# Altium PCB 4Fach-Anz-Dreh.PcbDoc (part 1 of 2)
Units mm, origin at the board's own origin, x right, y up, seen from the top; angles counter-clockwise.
Board outline 160 x 100 mm, 2 copper layers (Top Layer, Bottom Layer), stack 1.601 mm thick; 204 components, 197 nets, 945 pads, 254 vias.
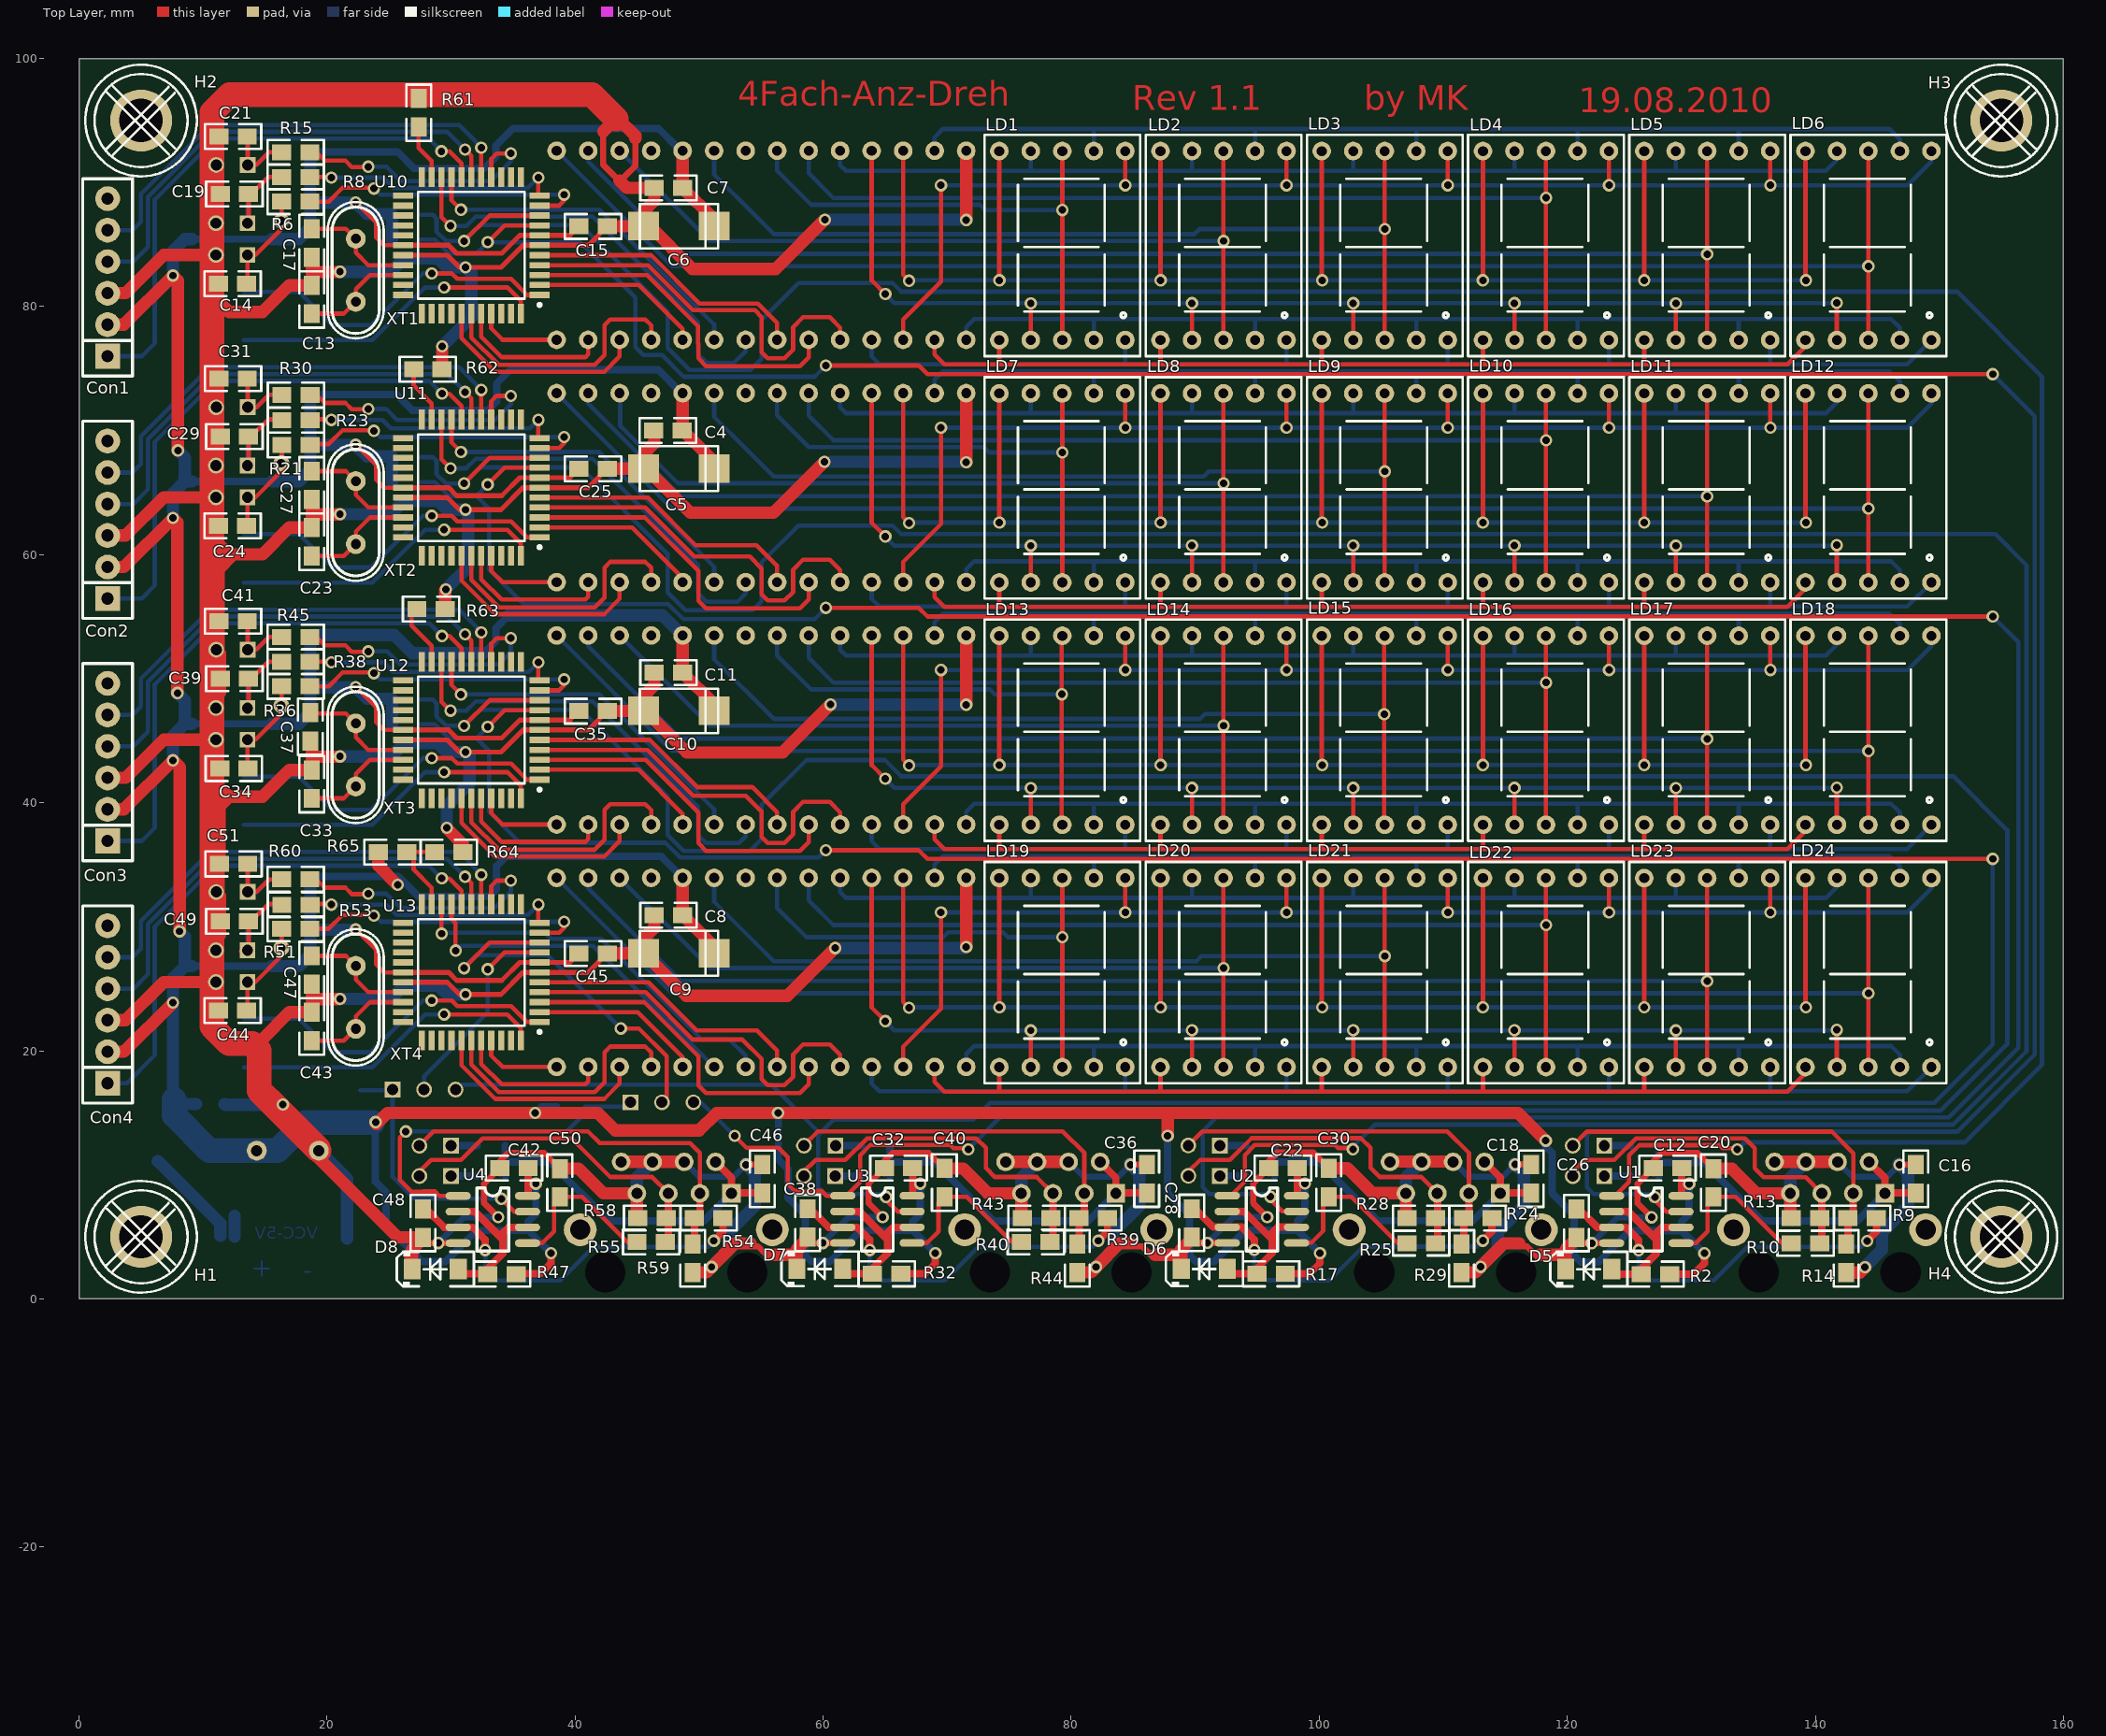
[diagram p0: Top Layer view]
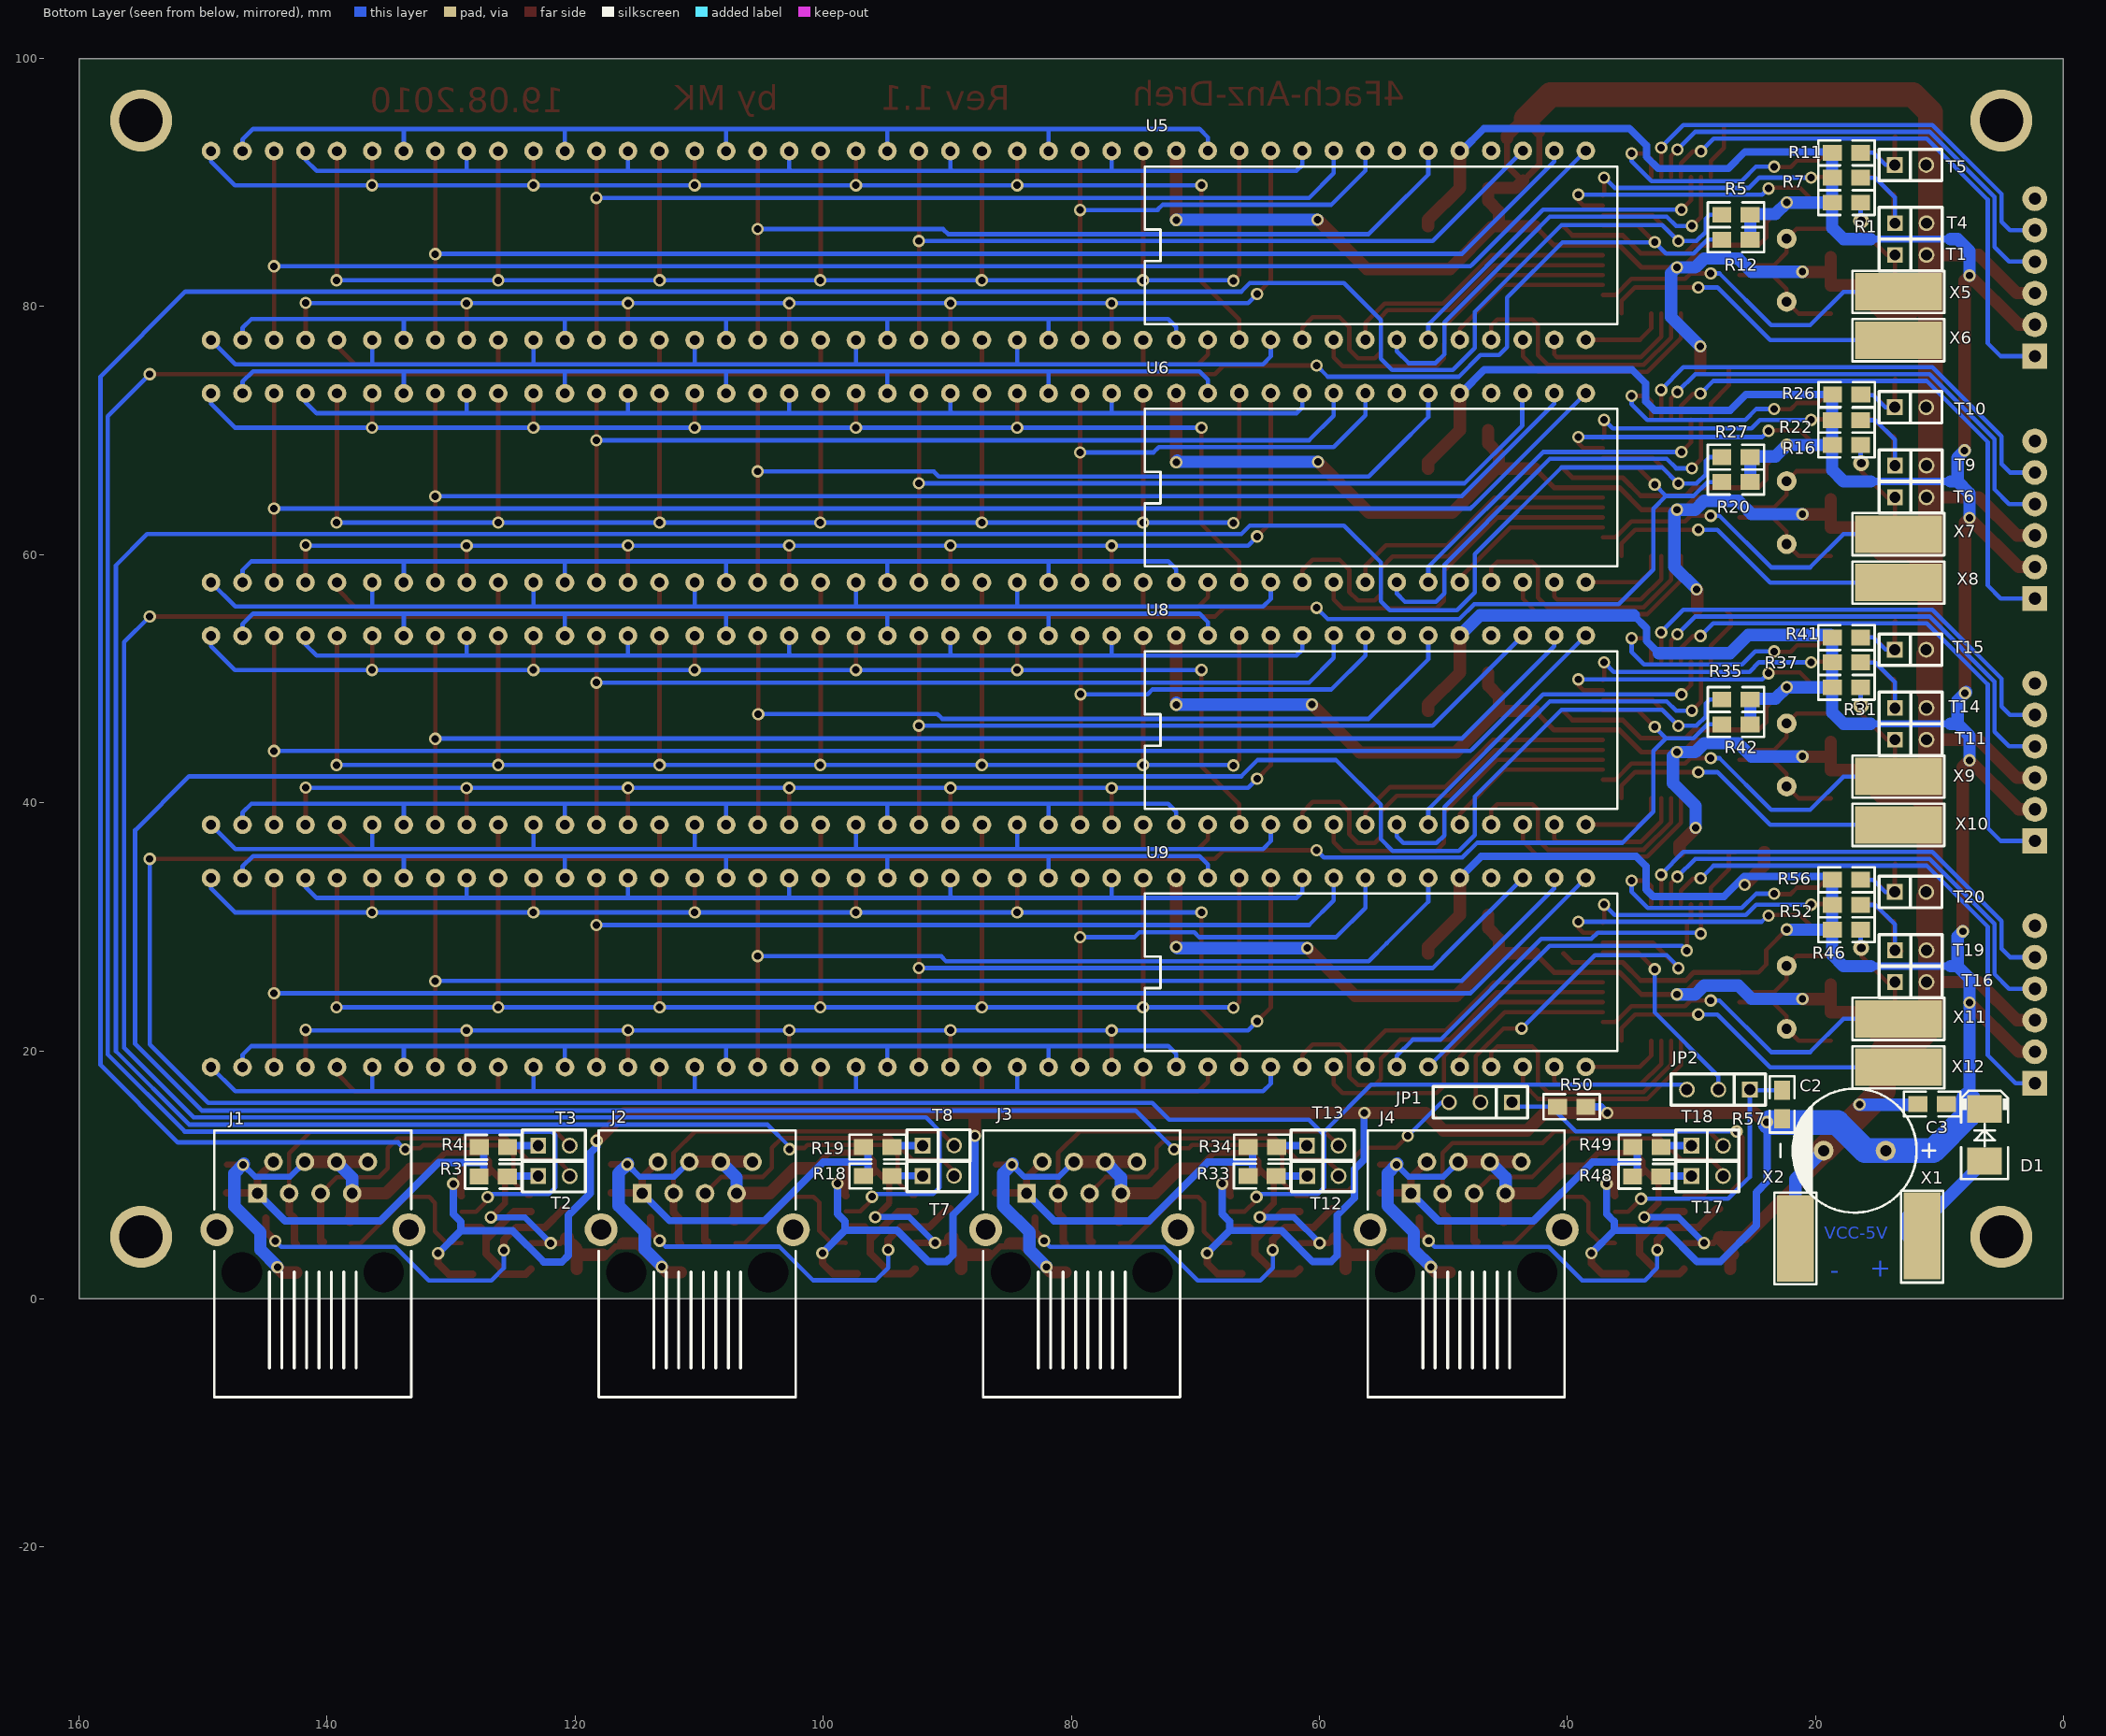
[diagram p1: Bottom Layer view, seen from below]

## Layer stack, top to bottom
Top Layer: signal copper 0.0356
Dielectric: core 1.53, FR-4, Dk 4.8
Bottom Layer: signal copper 0.0356

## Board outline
0,0 160,0 160,100 0,100

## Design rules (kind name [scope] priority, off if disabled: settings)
Clearance [All] p1: gap=0.2
ComponentClearance [All] p1 off: gap=0.254 collisioncheckmode=3 verticalgap=0 showdistances=FALSE
HoleSize [All] p1: absolutevalues=TRUE maxlimit=10 minlimit=0.2 maxpercent=80.000 minpercent=20.000
PlaneConnect [All] p1: planeconnectstyle=Relief reliefexpansion=0.5 reliefentries=4 reliefconductorwidth=0.2 reliefairgap=0.2
PolygonConnect [All] p1: connectstyle=Direct reliefconductorwidth=1 reliefentries=4 polygonreliefangle="90 Angle"
RoutingVias [All] p1: holewidth=0.4 width=0.8 viastyle="Through Hole" minholewidth=0.4 minwidth=0.8 maxholewidth=1 maxwidth=2
SolderMaskExpansion [All] p1: expansion=0.102
TestPointUsage [All] p1: valid=0 allowmultiple=FALSE
Testpoint [All] p1: side=3 testpointundercomponent=TRUE minsize=1.016 maxsize=2.54 preferedsize=1.524 minholesize=0 maxholesize=1.016 preferedholesize=0.813 testpointgrid=0.025 style=297 order=0123456789
Width [All] p1: maxlimit=10 minlimit=0.2 preferedwidth=0.5
16 further rules are at their usual default settings.

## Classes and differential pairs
component class PIC-3-4: C32 C33 C34 C35 C36 C37 C38 C39 C40 C41 C42 C43 C44 C45 C46 C47 C48 C49 C50 C51 Con3 Con4 D7 D8 J3 J4 JP1 JP2 R31 R32 R33 R34 R35 R36 R37 R38 R39 R40 R41 R42 R43 R44 R45 R46 R47 R48 R49 R50 R51 R52 R53 R54 R55 R56 R57 R58 R59 R60 R63 R64 R65 T11 T12 T13 T14 T15 T16 T17 T18 T19 T20 U3 U4 U12 U13 X9 X10 X11 X12 XT3 XT4
component class PIC-1-2: C12 C13 C14 C15 C16 C17 C18 C19 C20 C21 C22 C23 C24 C25 C26 C27 C28 C29 C30 C31 Con1 Con2 D5 D6 H1 H2 H3 H4 J1 J2 R1 R2 R3 R4 R5 R6 R7 R8 R9 R10 R11 R12 R13 R14 R15 R16 R17 R18 R19 R20 R21 R22 R23 R24 R25 R26 R27 R28 R29 R30 R61 R62 T1 T2 T3 T4 T5 T6 T7 T8 T9 T10 U1 U2 U10 U11 X5 X6 X7 X8 XT1 XT2
component class Display-3-4: C8 C9 C10 C11 LD13 LD14 LD15 LD16 LD17 LD18 LD19 LD20 LD21 LD22 LD23 LD24 U8 U9
component class Display-1-2: C2 C3 C4 C5 C6 C7 D1 LD1 LD2 LD3 LD4 LD5 LD6 LD7 LD8 LD9 LD10 LD11 LD12 U5 U6 X1 X2

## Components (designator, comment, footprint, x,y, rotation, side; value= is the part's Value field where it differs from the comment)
C2 "1000uF" ELK_RM050_10x12.5 16.83,11.95 r0 bottom
C3 "100nF" 0805 9.44,15.71 r0 bottom
C4 "100nF" 0805 48.63,70.02 r180 top
C5 "47uF 16V" Bauform_C 51.52,66.94 r180 top
C6 "47uF 16V" Bauform_C 51.52,86.48 r180 top locked
C7 "100nF" 0805 48.67,89.56 r180 top locked
C8 "100nF" 0805 48.67,30.94 r180 top
C9 "47uF 16V" Bauform_C 51.52,27.86 r180 top
C10 "47uF 16V" Bauform_C 51.52,47.4 r180 top
C11 "100nF" 0805 48.67,50.48 r180 top
C12 "100NF" 0805 129.22,10.54 r180 top locked
C13 "22PF" 0805 18.76,79.43 r90 top locked
C14 "100NF" 0805 13.52,81.85 r180 top locked
C15 "100nF" 0805 40.3,86.46 r0 top locked
C16 "100NF" 0805 148.09,8.53 r90 top locked
C17 "22PF" 0805 18.76,86.27 r270 top locked
C18 "100pF" 0805 120.74,7.25 r270 top locked
C19 "100NF" 0805 13.67,89.07 r180 top locked
C20 "100pF" 0805 131.77,8.21 r90 top locked
C21 "100NF" 0805 13.56,93.72 r180 top locked
C22 "100NF" 0805 98.22,10.55 r180 top
C23 "22PF" 0805 18.76,59.89 r90 top
C24 "100NF" 0805 13.52,62.31 r180 top
C25 "100nF" 0805 40.3,66.93 r0 top
C26 "100NF" 0805 117.09,8.54 r90 top
C27 "22PF" 0805 18.76,66.73 r270 top
C28 "100pF" 0805 89.71,7.26 r270 top
C29 "100NF" 0805 13.67,69.53 r180 top
C30 "100pF" 0805 100.77,8.22 r90 top
C31 "100NF" 0805 13.56,74.18 r180 top
C32 "100NF" 0805 67.22,10.55 r180 top
C33 "22PF" 0805 18.76,40.35 r90 top
C34 "100NF" 0805 13.63,42.75 r180 top
C35 "100nF" 0805 40.3,47.38 r0 top
C36 "100NF" 0805 86.09,8.54 r90 top
C37 "22PF" 0805 18.64,47.27 r270 top
C38 "100pF" 0805 58.74,7.26 r270 top
C39 "100NF" 0805 13.67,49.99 r180 top
C40 "100pF" 0805 69.77,8.22 r90 top
C41 "100NF" 0805 13.56,54.64 r180 top
C42 "100NF" 0805 36.21,10.54 r180 top
C43 "22PF" 0805 18.76,20.81 r90 top
C44 "100NF" 0805 13.52,23.23 r180 top
C45 "100nF" 0805 40.3,27.84 r0 top
C46 "100NF" 0805 55.08,8.53 r90 top
C47 "22PF" 0805 18.76,27.65 r270 top
C48 "100pF" 0805 27.73,7.25 r270 top
C49 "100NF" 0805 13.67,30.45 r180 top
C50 "100pF" 0805 38.76,8.21 r90 top
C51 "100NF" 0805 13.6,35.06 r180 top
Con1 "Con_6" Con_6 2.3,76 r90 top locked
Con2 "Con_6" Con_6 2.3,56.46 r90 top
Con3 "Con_6" Con_6 2.3,36.92 r90 top
Con4 "Con_6" Con_6 2.3,17.38 r90 top
D1 "MBRS140T3(R)" SMB 6.35,11.11 r270 bottom
D5 "LL4148" MINIMELF 123.58,2.4 r270 top locked
D6 "LL4148" MINIMELF 92.58,2.41 r270 top
D7 "LL4148" MINIMELF 61.58,2.41 r270 top
D8 "LL4148" MINIMELF 30.57,2.4 r270 top
H1 "Hole 3,5mm" "Hole 3,5mm" 5,5 r0 top locked
H2 "Hole 3,5mm" "Hole 3,5mm" 5,95 r0 top locked
H3 "Hole 3,5mm" "Hole 3,5mm" 155,95 r0 top locked
H4 "Hole 3,5mm" "Hole 3,5mm" 155,5 r0 top locked
J1 "MEBP 8-8G" "RJ45-JACK-MEBP 8-8G" 145.6,8.5 r180 bottom locked
J2 "MEBP 8-8G" "RJ45-JACK-MEBP 8-8G" 114.6,8.5 r180 bottom locked
J3 "MEBP 8-8G" "RJ45-JACK-MEBP 8-8G" 83.6,8.5 r180 bottom locked
J4 "MEBP 8-8G" "RJ45-JACK-MEBP 8-8G" 52.6,8.5 r180 bottom
JP1 "Jumper" SIP3 44.46,15.84 r0 bottom
JP2 "Jumper" SIP3 25.28,16.87 r0 bottom
LD1 "SA52-11" SA52-11 73,76 r0 top locked
LD2 "SA52-11" SA52-11 86,76 r0 top locked
LD3 "SA52-11" SA52-11 99,76 r0 top locked
LD4 "SA52-11" SA52-11 112,76 r0 top locked
LD5 "SA52-11" SA52-11 125,76 r0 top locked
LD6 "SA52-11" SA52-11 138,76 r0 top locked
LD7 "SA52-11" SA52-11 73,56.46 r0 top
LD8 "SA52-11" SA52-11 86,56.46 r0 top
LD9 "SA52-11" SA52-11 99,56.46 r0 top
LD10 "SA52-11" SA52-11 112,56.46 r0 top
LD11 "SA52-11" SA52-11 125,56.46 r0 top
LD12 "SA52-11" SA52-11 138,56.46 r0 top
LD13 "SA52-11" SA52-11 73,36.92 r0 top
LD14 "SA52-11" SA52-11 86,36.92 r0 top
LD15 "SA52-11" SA52-11 99,36.92 r0 top
LD16 "SA52-11" SA52-11 112,36.92 r0 top
LD17 "SA52-11" SA52-11 125,36.92 r0 top
LD18 "SA52-11" SA52-11 138,36.92 r0 top
LD19 "SA52-11" SA52-11 73,17.38 r0 top
LD20 "SA52-11" SA52-11 86,17.38 r0 top
LD21 "SA52-11" SA52-11 99,17.38 r0 top
LD22 "SA52-11" SA52-11 112,17.38 r0 top
LD23 "SA52-11" SA52-11 125,17.38 r0 top
LD24 "SA52-11" SA52-11 138,17.38 r0 top
R1 "1k" 0805 18.64,88.38 r180 bottom locked
R2 "1k" 0805 128.26,2 r180 top locked
R3 "1k" 0805 127.75,9.88 r180 bottom locked
R4 "1k" 0805 127.74,12.22 r180 bottom locked
R5 "1k" 0805 27.54,87.4 r180 bottom locked
R6 "1k" 0805 16.32,88.46 r0 top locked
R7 "1k" 0805 18.64,90.38 r180 bottom locked
R8 "1k" 0805 16.32,90.45 r0 top locked
R9 "1k" 0805 144.92,6.51 r180 top locked
R10 "1k" 0805 140.36,4.48 r180 top locked
R11 "1k" 0805 18.64,92.4 r180 bottom locked
R12 "1k" 0805 27.54,85.39 r180 bottom locked
R13 "100k" 0805 140.36,6.51 r180 top locked
R14 "100k" 0805 142.48,4.41 r270 top locked
R15 "1k" 0805 16.32,92.44 r0 top locked
R16 "1k" 0805 18.64,68.84 r180 bottom
R17 "1k" 0805 97.26,2.01 r180 top
R18 "1k" 0805 96.75,9.89 r180 bottom
R19 "1k" 0805 96.74,12.23 r180 bottom
R20 "1k" 0805 27.54,67.86 r180 bottom
R21 "1k" 0805 16.35,68.84 r0 top
R22 "1k" 0805 18.64,70.84 r180 bottom
R23 "1k" 0805 16.35,70.84 r0 top
R24 "1k" 0805 113.92,6.52 r180 top
R25 "1k" 0805 109.36,4.49 r180 top
R26 "1k" 0805 18.61,72.9 r180 bottom
R27 "1k" 0805 27.54,65.85 r180 bottom
R28 "100k" 0805 109.36,6.52 r180 top
R29 "100k" 0805 111.48,4.42 r270 top
R30 "1k" 0805 16.35,72.86 r0 top
R31 "1k" 0805 18.64,49.3 r180 bottom
R32 "1k" 0805 66.26,2.01 r180 top
R33 "1k" 0805 65.75,9.89 r180 bottom
R34 "1k" 0805 65.74,12.23 r180 bottom
R35 "1k" 0805 27.54,48.32 r180 bottom
R36 "1k" 0805 16.32,49.38 r0 top
R37 "1k" 0805 18.64,51.3 r180 bottom
R38 "1k" 0805 16.32,51.37 r0 top
R39 "1k" 0805 82.92,6.52 r180 top
R40 "1k" 0805 78.29,4.59 r180 top
R41 "1k" 0805 18.64,53.32 r180 bottom
R42 "1k" 0805 27.54,46.31 r180 bottom
R43 "100k" 0805 78.36,6.52 r180 top
R44 "100k" 0805 80.48,4.42 r270 top
R45 "1k" 0805 16.32,53.36 r0 top
R46 "1k" 0805 18.64,29.76 r180 bottom
R47 "1k" 0805 35.25,2 r180 top
R48 "1k" 0805 34.74,9.88 r180 bottom
R49 "1k" 0805 34.73,12.22 r180 bottom
R50 "1k" 0805 40.8,15.49 r180 bottom
R51 "1k" 0805 16.32,29.84 r0 top
R52 "1k" 0805 18.64,31.76 r180 bottom
R53 "1k" 0805 16.35,31.76 r0 top
R54 "1k" 0805 51.91,6.51 r180 top
R55 "1k" 0805 47.28,4.58 r180 top
R56 "1k" 0805 18.64,33.78 r180 bottom
R57 "1k" 0805 22.68,16.82 r270 bottom
R58 "100k" 0805 47.35,6.51 r180 top
R59 "100k" 0805 49.47,4.41 r270 top
R60 "1k" 0805 16.32,33.82 r0 top
R61 "100k" 0805 27.38,94.48 r90 top
R62 "100k" 0805 29.27,74.95 r180 top
R63 "100k" 0805 29.53,55.62 r180 top
R64 "100k" 0805 28.67,36.025 r0 top
R65 "100k" 0805 26.42,36.025 r180 top
T1 "Taster" SIP2 13.58,84.16 r180 bottom locked
T2 "Taster" SIP2 122.98,9.89 r180 bottom locked
T3 "Taster" SIP2 122.98,12.35 r180 bottom locked
T4 "Taster" SIP2 13.58,86.72 r180 bottom locked
T5 "Taster" SIP2 13.6,91.42 r180 bottom locked
T6 "Taster" SIP2 13.58,64.62 r180 bottom
T7 "Taster" SIP2 91.99,9.91 r180 bottom
T8 "Taster" SIP2 91.98,12.36 r180 bottom
T9 "Taster" SIP2 13.58,67.18 r180 bottom
T10 "Taster" SIP2 13.6,71.88 r180 bottom
T11 "Taster" SIP2 13.58,45.08 r180 bottom
T12 "Taster" SIP2 60.98,9.9 r180 bottom
T13 "Taster" SIP2 60.99,12.35 r180 bottom
T14 "Taster" SIP2 13.58,47.64 r180 bottom
T15 "Taster" SIP2 13.6,52.34 r180 bottom
T16 "Taster" SIP2 13.58,25.54 r180 bottom
T17 "Taster" SIP2 29.98,9.9 r180 bottom
T18 "Taster" SIP2 29.98,12.34 r180 bottom
T19 "Taster" SIP2 13.58,28.1 r180 bottom
T20 "Taster" SIP2 13.6,32.8 r180 bottom
U1 "LM393M" SO-8 123.58,8.3 r0 top locked
U2 "LM393M" SO-8 92.58,8.31 r0 top
U3 "LM393M" SO-8 61.58,8.31 r0 top
U4 "LM393M" SO-8 30.57,8.3 r0 top
U5 "ICM7218AIJI" ICM7218AIJM 71.53,77.32 r90 bottom locked
U6 "ICM7218AIJI" ICM7218AIJM 71.53,57.78 r90 bottom
U8 "ICM7218AIJI" ICM7218AIJM 71.53,38.24 r90 bottom
U9 "ICM7218AIJI" ICM7218AIJM 71.53,18.7 r90 bottom
U10 "16F887" TQFP-44 37.13,80.94 r180 top locked
U11 "16F887" TQFP-44 37.13,61.4 r180 top
U12 "16F887" TQFP-44 37.13,41.86 r180 top
U13 "16F887" TQFP-44 37.13,22.32 r180 top
X1 "Ground" GND_PAD3#1 11.39,5.01 r270 bottom
X2 "Ground" GND_PAD3#2 21.6,4.87 r270 bottom
X5 "Ground" GND_PAD3#2 13.3,81.19 r0 bottom locked
X6 "Ground" GND_PAD3#2 13.3,77.29 r0 bottom locked
X7 "Ground" GND_PAD3#2 13.3,61.65 r180 bottom
X8 "Ground" GND_PAD3#2 13.3,57.75 r0 bottom
X9 "Ground" GND_PAD3#2 13.3,42.11 r180 bottom
X10 "Ground" GND_PAD3#2 13.3,38.21 r0 bottom
X11 "Ground" GND_PAD3#2 13.3,22.57 r180 bottom
X12 "Ground" GND_PAD3#2 13.3,18.67 r0 bottom
XT1 "20MHz" HC-49/U_ST 22.31,80.39 r90 top locked
XT2 "20MHz" HC-49/U_ST 22.31,60.85 r90 top
XT3 "20MHz" HC-49/U_ST 22.31,41.31 r90 top
XT4 "20MHz" HC-49/U_ST 22.31,21.77 r90 top

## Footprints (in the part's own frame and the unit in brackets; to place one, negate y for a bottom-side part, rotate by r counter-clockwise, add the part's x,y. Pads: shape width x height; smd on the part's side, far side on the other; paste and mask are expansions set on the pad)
0805 [mm] "0805_0_0197_R"
  rect 1.54x1.28 smd: 1(0,0) 2(2.29,0)
  silkscreen extent -1.13,-1 3.42,1
Bauform_C [mm] "Tantal 47uF 16V 6032"
  rect 2.5x2.3 smd: 1(0.3,0) 2(6,0)
  silkscreen extent 0,-1.8 6.3,1.8
Con_6 [mm] "Pic-Prog-Connector"
  rect 2x2 hole 1: 1(0,0)
  round 2 hole 1: 2(2.54,0) 3(5.08,0) 4(7.62,0) 5(10.16,0) 6(12.7,0)
  silkscreen extent -1.6,-2 14.3,2
ELK_RM050_10x12.5 [mm]
  round 1.6 hole 0.9: 1(-2.5,0) 2(2.5,0)
  silkscreen extent -6.5,-5 5.99,5
GND_PAD3#1 [mm]
  rect 7x3 smd: 1(-0.06,0)
  silkscreen extent -3.7,-1.7 3.7,1.7
GND_PAD3#2 [mm]
  rect 7x3 smd: 1(0,0)
  silkscreen extent -3.7,-1.7 3.7,1.7
HC-49/U_ST [mm]
  round 1.6 hole 0.8: 1(0,0) 2(5.08,0)
  silkscreen extent -2.96,-2.25 8.04,2.27
"Hole 3,5mm" [mm]
  round 5 hole 3.5: 1(0,0)
  silkscreen extent -4.5,-4.5 4.5,4.5
ICM7218AIJM [mm] "7-Segment Driver"
  round 1.5 hole 0.8: 1(0,0) 2(0,-2.54) 3(0,-5.08) 4(0,-7.62) 5(0,-10.16) 6(0,-12.7) 7(0,-15.24) 8(0,-17.78) 9(0,-20.32) 10(0,-22.86) 11(0,-25.4) 12(0,-27.94) 13(0,-30.48) 14(0,-33.02) 15(15.24,-33.02) 16(15.24,-30.48) 17(15.24,-27.94) 18(15.24,-25.4) 19(15.24,-22.86) 20(15.24,-20.32) 21(15.24,-17.78) 22(15.24,-15.24) 23(15.24,-12.7) 24(15.24,-10.16) 25(15.24,-7.62) 26(15.24,-5.08) 27(15.24,-2.54) 28(15.24,0)
  silkscreen extent 1.27,-35.56 13.97,2.54
MINIMELF [mil]
  rect 64x54 smd: A(0,0) K(0,-146)
  silkscreen extent -55,-195 55,50
"RJ45-JACK-MEBP 8-8G" [mm] "Connector; PCB Jack, Thru-Hole; 1-Port, 8 Positions, 8 Loaded; Shielded without Lightpipes; Left Angle"
  rect 1.5x1.5 hole 0.9: 1(0,0)
  round 1.5 hole 0.9: 2(1.27,2.54) 3(2.54,0) 4(3.81,2.54) 5(5.08,0) 6(6.35,2.54) 7(7.62,0) 8(8.89,2.54)
  round 2.65 hole 1.6: MH1(-3.3,-2.921) MH2(12.19,-2.921)
  round 2.95 hole 3.25: MH3(-1.27,-6.35) MH4(10.16,-6.35)
  silkscreen extent -3.49,-16.42 12.38,5.08
SA52-11 [mm] "7-Segment-Anzeige 13mm"
  round 1.5 hole 0.8: 1(1.2,1.3) 2(3.74,1.3) 3(6.28,1.3) 4(8.82,1.3) 5(11.36,1.3) 6(11.36,16.54) 7(8.82,16.54) 8(6.28,16.54) 9(3.74,16.54) 10(1.2,16.54)
  silkscreen extent 0,0 12.56,17.84
SIP2 [mm]
  rect 1.27x1.27 hole 0.9: 1(0,0)
  round 1.27 hole 0.9: 2(2.54,0)
  silkscreen extent -1.27,-1.27 3.81,1.27
SIP3 [mm]
  rect 1.27x1.27 hole 0.9: 1(0,0)
  round 1.27 hole 0.9: 2(2.54,0) 3(5.08,0)
  silkscreen extent -1.27,-1.27 6.35,1.27
SMB [mm]
  rect 2.2x2.8 smd: A(0,0) K(-4.2,0)
  silkscreen extent -5.66,-1.9 1.46,1.9
SO-8 [mil]
  oval 80x24 smd: 1(0,0) 2(0,-50) 3(0,-100) 4(0,-150) 5(220,-150) 6(220,-100) 7(220,-50) 8(220,0)
  silkscreen extent 60,-175 160,25
TQFP-44 [mm]
  rect 1.6x0.5 smd: 1(0,0) 2(0,-0.8) 3(0,-1.6) 4(0,-2.4) 5(0,-3.2) 6(0,-4) 7(0,-4.8) 8(0,-5.6) 9(0,-6.4) 10(0,-7.2) 11(0,-8) 23(11,-8) 24(11,-7.2) 25(11,-6.4) 26(11,-5.6) 27(11,-4.8) 28(11,-4) 29(11,-3.2) 30(11,-2.4) 31(11,-1.6) 32(11,-0.8) 33(11,0)
  rect 0.5x1.6 smd: 12(1.5,-9.5) 13(2.3,-9.5) 14(3.1,-9.5) 15(3.9,-9.5) 16(4.7,-9.5) 17(5.5,-9.5) 18(6.3,-9.5) 19(7.1,-9.5) 20(7.9,-9.5) 21(8.7,-9.5) 22(9.5,-9.5) 34(9.5,1.5) 35(8.7,1.5) 36(7.9,1.5) 37(7.1,1.5) 38(6.3,1.5) 39(5.5,1.5) 40(4.7,1.5) 41(3.9,1.5) 42(3.1,1.5) 43(2.3,1.5) 44(1.5,1.5)
  silkscreen extent -0.13,-8.3 9.8,0.92

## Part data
C2: library part 1000UF_RM5_25V, "Capacitor Aluminum Electrolytic, 1000UF, 25V, 20%, 105°C, Low impedance"
C3 C4 C7 C8 C11 C12 C14 C15 C16 C19 C21 C22 C24 C25 C26 C29 C31 C32 C34 C35 C36 C39 C41 C42 C44 C45 C46 C49 C51: library part 100NF_0805, "SMD Kondensator"
C5 C6 C9 C10: library part "TR3 Tantal 47uF 16V", "Tantal 47uF 16V"
C13 C17 C23 C27 C33 C37 C43 C47: library part 68PF_0805, "SMD Kondensator"
C18 C20 C28 C30 C38 C40 C48 C50: library part 100PF_0805, "Capacitor SMD"
D1: library part MBRS140T3(R)_SMB, "Schottkydiode _SMD"
D5 D6 D7 D8: "Universal diode SMD"
J1 J2 J3 J4: library part "RJ45-JACK-MEBP 8-8G", "Right Angle, Standard Profile, External Shield PCB Jack"
JP1 JP2: library part JUMPER3, "Lötaugen"
LD1 LD2 LD3 LD4 LD5 LD6 LD7 LD8 LD9 LD10 LD11 LD12 LD13 LD14 LD15 LD16 LD17 LD18 LD19 LD20 LD21 LD22 LD23 LD24: "7-Segment-Anzeige 13mm"
R1 R2 R3 R4 R5 R6 R7 R8 R9 R10 R11 R12 R15 R16 R17 R18 R19 R20 R21 R22 R23 R24 R25 R26 R27 R30 R31 R32 R33 R34 R35 R36 R37 R38 R39 R40 R41 R42 R45 R46 R47 R48 R49 R50 R51 R52 R53 R54 R55 R56 R57 R60: library part 1k_0805, "SMD Resistor"
R13 R14 R28 R29 R43 R44 R58 R59 R61 R62 R63 R64 R65: library part 100K_0805, "SMD Resistor"
T1 T2 T3 T4 T5 T6 T7 T8 T9 T10 T11 T12 T13 T14 T15 T16 T17 T18 T19 T20: library part TASTER_SCH
U1 U2 U3 U4: library part LM393_SO-8, "Dual Differential Comperator"
U10 U11 U12 U13: library part PIC-16F887, "CPU"
X1 X2 X5 X6 X7 X8 X9 X10 X11 X12: library part GND_PAD3, "Groundpad"
XT1 XT2 XT3 XT4: library part XTAL, "Crystal Oscillator"

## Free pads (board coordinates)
  oval 2x0 on Mech1: 0(99.31,-29.63) 0(149.35,16.73) 0(149.35,36.27) 0(149.35,55.81) 0(149.35,75.35)

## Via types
v1: diameter 1, hole 0.6, Top Layer to Bottom Layer, 249 vias
v2: diameter 1.27, hole 0.711, Top Layer to Bottom Layer, 5 vias

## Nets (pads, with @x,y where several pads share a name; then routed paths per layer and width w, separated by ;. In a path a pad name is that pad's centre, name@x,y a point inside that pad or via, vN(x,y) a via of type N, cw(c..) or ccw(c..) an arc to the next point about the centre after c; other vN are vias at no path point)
/WRITE-1: U5.8 U10.20 | length 36.1
  Top Layer w0.35: U10.20@29.23,90.44 29.23,87.22 v1(29.95,86.5)
  Bottom Layer w0.35: v1(29.95,86.5) 31.23,86.5 31.99,87.26 41.41,87.26 42.99,85.68 ; 42.98,85.67 49.92,78.73 49.92,76.15 50.63,75.44 52.79,75.44 53.75,76.4 U5.8@53.75,77.32
/WRITE-2: U6.8 U11.20 | length 35.7
  Top Layer w0.35: U11.20@29.23,70.9 29.23,67.68 v1(29.95,66.96)
  Bottom Layer w0.35: v1(29.95,66.96) 31.23,66.96 31.99,67.72 41.41,67.72 42.99,66.14 ; 42.98,66.13 49.92,59.19 49.92,56.88 50.6,56.2 53.09,56.2 53.75,56.86 U6.8@53.75,57.78
/WRITE-3: U8.8 U12.20 | length 35.8
  Top Layer w0.35: U12.20@29.23,51.36 29.23,48.14 v1(29.95,47.42)
  Bottom Layer w0.35: v1(29.95,47.42) 31.23,47.42 31.99,48.18 41.41,48.18 42.99,46.6 ; 42.98,46.59 49.92,39.65 49.92,37.37 50.54,36.75 53.23,36.75 53.75,37.27 U8.8@53.75,38.24 U8.8@53.65,38.14
/WRITE-4: U9.8 U13.20 | length 31.9
  Top Layer w0.35: v1(29.23,29.44) U13.20@29.23,31.82
  Bottom Layer w0.35: v1(29.23,29.44) 29.31,29.52 37.56,29.52 38.06,29.02 42.11,29.02 50.23,20.9 52.45,20.9 53.75,19.6 U9.8@53.75,18.7
CLK-1: Con1.5 U10.16 | length 39.2
  Top Layer w0.35: 32.43,91.47 U10.16@32.43,90.44 v1(32.43,92.81) ; v1(32.43,92.81) 32.43,92.85 v1(32.43,92.81)
  Bottom Layer w0.35: v1@32.43,92.85 30.635,94.645 10.569,94.645 5,89.076 5,86.84 4.32,86.16 Con1.5@2.37,86.16 ; Con1.5@2.37,86.16 Con1.5@2.3,86.16 Con1.5@2.37,86.16
CLK-2: Con2.5 U11.16 | length 39.2
  Top Layer w0.35: 32.43,71.93 U11.16@32.43,70.9 v1(32.43,73.27) ; v1(32.43,73.27) 32.43,73.31 v1(32.43,73.27)
  Bottom Layer w0.35: v1@32.43,73.31 30.635,75.105 10.569,75.105 5,69.536 5,67.3 4.32,66.62 Con2.5@2.37,66.62 ; Con2.5@2.37,66.62 Con2.5@2.3,66.62 Con2.5@2.37,66.62
CLK-3: Con3.5 U12.16 | length 39.2
  Top Layer w0.35: 32.43,52.39 U12.16@32.43,51.36 v1(32.43,53.73) ; v1(32.43,53.73) 32.43,53.77 v1(32.43,53.73)
  Bottom Layer w0.35: v1@32.43,53.77 30.635,55.565 29.57,55.565 10.569,55.565 5,49.996 5,47.76 4.32,47.08 Con3.5@2.37,47.08 ; Con3.5@2.37,47.08 Con3.5@2.3,47.08 Con3.5@2.37,47.08
CLK-4: Con4.5 U13.16 | length 39.2
  Top Layer w0.35: 32.43,32.85 U13.16@32.43,31.82 v1(32.43,34.19) ; v1(32.43,34.19) 32.43,34.23 v1(32.43,34.19)
  Bottom Layer w0.35: v1@32.43,34.23 30.635,36.025 10.569,36.025 5,30.456 5,28.22 4.32,27.54 Con4.5@2.37,27.54 ; Con4.5@2.37,27.54 Con4.5@2.3,27.54 Con4.5@2.37,27.54
CLOCK_MES-1: R12.1 U1.7 U10.8 | length 247.7
  Top Layer w0.35: v1(32.95,85.19) 34.3,86.54 U10.8@37.13,86.54 ; v1(60.22,75.25) 67.7,75.25 68.4,74.55 v1(154.3,74.55) ; v1(127.06,8.21) 127.06,7.96 127.99,7.03 U1.7@129.168,7.03
  Bottom Layer w0.35: R12.1@27.54,85.39 28.692,85.39 29.812,84.27 32.03,84.27 v1(32.95,85.19) 40.39,85.19 44.85,80.73 44.85,76.74 45.5,76.09 47,76.09 48.75,74.34 59.31,74.34 v1(60.22,75.25) ; v1(127.06,8.21) 126.83,8.44 122.12,8.44 121.59,8.97 121.59,13.195 121.88,13.485 151.485,13.485 157.7,19.7 157.7,71.15 v1(154.3,74.55)
CLOCK_MES-2: R27.1 U2.7 U11.8 | length 259.5
  Top Layer w0.35: v1(32.95,65.65) 34.3,67 U11.8@37.13,67 ; v1(60.22,55.71) 67.7,55.71 68.4,55.01 v1(154.3,55.01) ; v1(96.07,8.23) 96.07,7.98 97,7.05 U2.7@98.178,7.05
  Bottom Layer w0.35: R27.1@27.54,65.85 28.692,65.85 29.812,64.73 32.03,64.73 ; v1(60.22,55.71) 59.31,54.8 48.72,54.8 47.51,56.01 35.86,56.01 33.06,58.81 33.06,63.7 32.03,64.73 ; v1(96.07,8.23) 95.84,8.46 91.13,8.46 90.6,8.99 90.6,13.52 91.71,14.63 150.77,14.63 156.37,20.23 156.37,52.94 v1(154.3,55.01) ; 32.03,64.73 v1(32.95,65.65) 32.03,64.73
CLOCK_MES-3: JP2.3 R42.1 U3.7 U12.8 | length 297
  Top Layer w0.35: v1(32.95,46.11) 34.3,47.46 U12.8@37.13,47.46 ; v1(60.22,36.17) 67.7,36.17 68.4,35.47 v1(154.3,35.47) ; v1(65.06,8.22) 65.06,7.97 65.99,7.04 U3.7@67.168,7.04
  Bottom Layer w0.35: R42.1@27.54,46.31 28.692,46.31 29.812,45.19 32.03,45.19 ; JP2.3@30.36,16.87 30.75,17.26 45.24,17.26 55.81,17.26 59.575,13.495 ; v1(32.95,46.11) 32.03,45.19 ; v1(60.22,36.17) 59.62,35.57 48.46,35.57 47.26,36.77 35.56,36.77 33.06,39.27 33.06,44.16 32.03,45.19 ; v1(65.06,8.22) 64.83,8.45 60.12,8.45 59.59,8.98 59.59,13.205 60.825,14.44 72.11,14.44 73.47,15.8 149.59,15.8 154.3,20.51 v1(154.3,35.47)
CLOCK_MES-4: JP2.2 U13.8 | length 16.6
  Top Layer w0.35: v1(32.95,26.57) 34.3,27.92 U13.8@37.13,27.92
  Bottom Layer w0.35: JP2.2@27.82,16.87 27.82,17.96 32.95,23.09 v1(32.95,26.57)
CLOCK_MES-4A: JP2.1 R57.1 U4.7 | length 21.7
  Top Layer w0.35: v1(34.05,8.07) 35.09,7.03 U4.7@36.158,7.03
  Bottom Layer w0.35: R57.1@22.68,16.82 25.23,16.82 JP2.1@25.28,16.87 25.28,9.83 27.04,8.07 v1(34.05,8.07)
DAT-1: Con1.4 U10.17 | length 38.7
  Top Layer w0.35: v1(31.13,92.65) 31.63,92.15 U10.17@31.63,90.44 U10.17@31.63,90.54
  Bottom Layer w0.35: Con1.4@2.3,83.62 4.37,83.62 5.55,84.8 5.55,88.848 10.797,94.095 24.245,94.095 29.685,94.095 v1(31.13,92.65)
DAT-2: Con2.4 U11.17 | length 38.7
  Top Layer w0.35: v1(31.13,73.11) 31.63,72.61 U11.17@31.63,70.9 U11.17@31.63,71
  Bottom Layer w0.35: Con2.4@2.3,64.08 4.37,64.08 5.55,65.26 5.55,69.308 10.797,74.555 24.245,74.555 29.685,74.555 v1(31.13,73.11)
DAT-3: Con3.4 U12.17 | length 38.7
  Top Layer w0.35: v1(31.13,53.57) 31.63,53.07 U12.17@31.63,51.36 U12.17@31.63,51.46
  Bottom Layer w0.35: Con3.4@2.3,44.54 4.37,44.54 5.55,45.72 5.55,49.768 10.797,55.015 24.245,55.015 29.685,55.015 v1(31.13,53.57)
DAT-4: Con4.4 U13.17 | length 38.7
  Top Layer w0.35: v1(31.13,34.03) 31.63,33.53 U13.17@31.63,31.82 U13.17@31.63,31.92
  Bottom Layer w0.35: Con4.4@2.3,25 4.37,25 5.55,26.18 5.55,30.228 10.797,35.475 24.245,35.475 29.685,35.475 v1(31.13,34.03)
DATA_MES-1: R5.1 U1.1 U10.9 | length 250.3
  Top Layer w0.35: v1(31.04,85.28) 33.1,87.34 U10.9@37.13,87.34 ; U1.1@123.58,8.3 123.85,8.3 124.98,9.43 124.98,11.57 125.795,12.385 132.26,12.385 132.505,12.14 133.6,12.14 v1(133.7,12.04)
  Bottom Layer w0.35: R5.1@27.54,87.4 28.53,87.4 28.82,87.11 28.82,86.04 29.58,85.28 v1(31.04,85.28) ; v1@30.99,85.33 v1(31.04,85.28) ; v1(133.7,12.04) 134.27,12.61 152.03,12.61 158.27,18.85 158.27,74.37 151.435,81.205 66.285,81.205 65.605,81.885 58.005,81.885 55.04,78.92 55.04,75.79 54.14,74.89 49.22,74.89 47.46,76.65 47.46,79.58 40.47,86.57 32.35,86.57 31.06,85.28 v1(31.04,85.28)
DATA_MES-2: R20.1 U2.1 U11.9 | length 261.1
  Top Layer w0.35: v1(31.04,65.74) 33.1,67.8 U11.9@37.13,67.8 ; U2.1@92.59,8.32 92.86,8.32 93.99,9.45 93.99,11.59 94.805,12.405 101.27,12.405 101.515,12.16 102.61,12.16 v1(102.71,12.06)
  Bottom Layer w0.35: R20.1@27.54,67.86 28.53,67.86 28.82,67.57 28.82,66.5 29.58,65.74 v1(31.04,65.74) ; v1@30.99,65.79 v1(31.04,65.74) ; v1@102.61,12.16 104.5,14.05 151.12,14.05 157.03,19.96 157.03,59.145 154.51,61.665 66.285,61.665 65.605,62.345 58.005,62.345 55.04,59.38 55.04,56.25 54.32,55.53 48.88,55.53 47.46,56.95 47.46,60.04 40.47,67.03 32.35,67.03 31.06,65.74 v1(31.04,65.74)
DATA_MES-3: JP1.3 R35.1 U3.1 U12.9 | length 286.3
  Top Layer w0.35: v1(31.04,46.2) 33.1,48.26 U12.9@37.13,48.26 ; v1(52.86,13.14) 53.81,12.19 55.45,12.19 56.39,12.19 57.15,11.43 57.15,9.25 57.69,8.71 59.86,8.71 60.26,8.31 U3.1@61.58,8.31 61.85,8.31 62.98,9.44 62.98,11.58 63.795,12.395 70.26,12.395 70.505,12.15 71.6,12.15 v1(71.7,12.05)
  Bottom Layer w0.35: R35.1@27.54,48.32 28.53,48.32 28.82,48.03 28.82,46.96 29.58,46.2 v1(31.04,46.2) ; v1@30.99,46.25 v1(31.04,46.2) ; JP1.3@49.62,15.81 50.19,15.81 v1(52.86,13.14) ; 72.27,12.62 v1(71.7,12.05) 74.83,15.18 82.89,15.18 ; 82.05,15.18 82.89,15.18 ; v1(31.04,46.2) 31.06,46.2 32.35,47.49 40.47,47.49 47.46,40.5 47.46,37.39 48.73,36.12 54.08,36.12 55.03,37.07 55.04,37.07 55.04,39.84 58.64,43.44 64.97,43.44 66.285,42.125 151.14,42.125 155.48,37.785 155.48,20.54 150.12,15.18 82.89,15.18
DATA_MES-4: JP1.2 U13.9 | length 31.1
  Top Layer w0.35: v1(31.04,26.66) 33.1,28.72 U13.9@37.13,28.72 ; v1(43.68,21.8) 45.14,21.8 47.38,19.56 47.38,16.11 JP1.2@47.08,15.81
  Bottom Layer w0.35: v1@31.06,26.66 v1(31.04,26.66) 30.99,26.71 31.99,27.71 37.77,27.71 v1(43.68,21.8)
DATA_MES-4A: JP1.1 R50.1 U4.1 | length 28.8
  Top Layer w0.35: v1(26.345,13.495) 25.87,13.02 25.87,9.58 26.82,8.63 27.71,8.63 ; 27.71,8.66 28.69,8.66 29.05,8.3 U4.1@30.57,8.3
  Bottom Layer w0.35: v1(26.345,13.495) 39.315,13.495 40.8,14.98 R50.1@40.8,15.49 44.22,15.49 JP1.1@44.54,15.81
DIGIT-1-1: LD6.3 LD6.8 U5.15 | length 124.9
  Top Layer w0.35: LD6.3@144.28,77.3 LD6.8@144.28,92.54
  Bottom Layer w0.35: U5.15@38.51,92.56 47.7,83.37 47.82,83.25 v1(144.28,83.25)
DIGIT-1-2: LD12.3 LD12.8 U6.15 | length 124.9
  Top Layer w0.35: LD12.3@144.28,57.76 LD12.8@144.28,73
  Bottom Layer w0.35: U6.15@38.51,73.02 47.7,63.83 47.82,63.71 v1(144.28,63.71)
DIGIT-1-3: LD18.3 LD18.8 U8.15 | length 124.9
  Top Layer w0.35: LD18.3@144.28,38.22 LD18.8@144.28,53.46
  Bottom Layer w0.35: U8.15@38.51,53.48 47.7,44.29 47.82,44.17 v1(144.28,44.17)
DIGIT-1-4: LD24.3 LD24.8 U9.15 | length 124.9
  Top Layer w0.35: LD24.3@144.28,18.68 LD24.8@144.28,33.92
  Bottom Layer w0.35: U9.15@38.51,33.94 47.7,24.75 47.82,24.63 v1(144.28,24.63)
DIGIT-2-1: LD5.3 LD5.8 U5.16 | length 109.4
  Top Layer w0.35: LD5.3@131.28,77.3 v1(131.28,84.23) LD5.8@131.28,92.54
  Bottom Layer w0.35: U5.16@41.05,92.56 41.05,91.7 48.5,84.25 131.26,84.25 v1(131.28,84.23)
DIGIT-2-2: LD11.3 LD11.8 U6.16 | length 109.4
  Top Layer w0.35: LD11.3@131.28,57.76 v1(131.28,64.69) LD11.8@131.28,73
  Bottom Layer w0.35: U6.16@41.05,73.02 41.05,72.16 48.5,64.71 131.26,64.71 v1(131.28,64.69)
DIGIT-2-3: LD17.3 LD17.8 U8.16 | length 109.4
  Top Layer w0.35: LD17.3@131.28,38.22 v1(131.28,45.15) LD17.8@131.28,53.46
  Bottom Layer w0.35: U8.16@41.05,53.48 41.05,52.62 48.5,45.17 131.26,45.17 v1(131.28,45.15)
DIGIT-2-4: LD23.3 LD23.8 U9.16 | length 109.4
  Top Layer w0.35: LD23.3@131.28,18.68 v1(131.28,25.61) LD23.8@131.28,33.92
  Bottom Layer w0.35: U9.16@41.05,33.94 41.05,33.08 48.5,25.63 131.26,25.63 v1(131.28,25.61)
DIGIT-3-1: LD4.3 LD4.8 U5.23 | length 77.3
  Top Layer w0.35: LD4.3@118.28,77.3 v1(118.28,88.76) LD4.8@118.28,92.54
  Bottom Layer w0.35: U5.23@58.83,92.56 58.83,90.75 60.82,88.76 v1(118.28,88.76)
DIGIT-3-2: LD10.3 LD10.8 U6.23 | length 77.3
  Top Layer w0.35: LD10.3@118.28,57.76 v1(118.28,69.22) LD10.8@118.28,73
  Bottom Layer w0.35: U6.23@58.83,73.02 58.83,71.21 60.82,69.22 v1(118.28,69.22)
DIGIT-3-3: LD16.3 LD16.8 U8.23 | length 77.3
  Top Layer w0.35: LD16.3@118.28,38.22 v1(118.28,49.68) LD16.8@118.28,53.46
  Bottom Layer w0.35: U8.23@58.83,53.48 58.83,51.67 60.82,49.68 v1(118.28,49.68)
DIGIT-3-4: LD22.3 LD22.8 U9.23 | length 77.3
  Top Layer w0.35: LD22.3@118.28,18.68 v1(118.28,30.14) LD22.8@118.28,33.92
  Bottom Layer w0.35: U9.23@58.83,33.94 58.83,32.13 60.82,30.14 v1(118.28,30.14)
DIGIT-4-1: LD3.3 LD3.8 U5.20 | length 73.4
  Top Layer w0.35: LD3.3@105.28,77.3 v1(105.28,86.25) LD3.8@105.28,92.54
  Bottom Layer w0.35: U5.20@51.21,92.56 51.21,90.64 54.578,87.272 56.01,85.84 72.4,85.84 89.94,85.84 90.31,86.21 90.31,86.25 v1(105.28,86.25)
DIGIT-4-2: LD9.3 LD9.8 U6.20 | length 73.4
  Top Layer w0.35: LD9.3@105.28,57.76 v1(105.28,66.71) LD9.8@105.28,73
  Bottom Layer w0.35: U6.20@51.21,73.02 51.21,71.1 53.888,68.422 56.01,66.3 73.9,66.3 90.69,66.3 91.05,66.66 ; 91.05,66.71 v1(105.28,66.71)
DIGIT-4-3: LD15.3 LD15.8 U8.20 | length 73.7
  Top Layer w0.35: LD15.3@105.28,38.22 105.24,38.26 v1(105.24,47.14) 105.24,53.42 LD15.8@105.28,53.46
  Bottom Layer w0.35: U8.20@51.21,53.48 51.21,51.56 56.01,46.76 71.02,46.76 90.4,46.76 90.8,47.16 104.12,47.16 ; 104.405,47.16 104.12,47.16 ; v1(105.24,47.14) 105.22,47.16 104.12,47.16
DIGIT-4-4: LD21.3 LD21.8 U9.20 | length 73.4
  Top Layer w0.35: LD21.3@105.28,18.68 v1(105.28,27.63) LD21.8@105.28,33.92
  Bottom Layer w0.35: U9.20@51.21,33.94 51.21,32.02 54.564,28.666 56.01,27.22 90.1,27.22 90.47,27.59 90.47,27.63 v1(105.28,27.63)
DIGIT-5-1: LD2.3 LD2.8 U5.17 | length 68.7
  Top Layer w0.35: LD2.3@92.28,77.3 LD2.8@92.28,92.54
  Bottom Layer w0.35: U5.17@43.59,92.56 49.27,86.88 ; 50.49,85.66 49.27,86.88 ; v1(92.28,85.29) 50.86,85.29 49.27,86.88
DIGIT-5-2: LD8.3 LD8.8 U6.17 | length 68.5
  Top Layer w0.35: LD8.3@92.28,57.76 v1(92.28,65.75) LD8.8@92.28,73
  Bottom Layer w0.35: U6.17@43.59,73.02 43.63,73.02 43.63,70.4 48.28,65.75 v1(92.28,65.75)
DIGIT-5-3: LD14.3 LD14.8 U8.17 | length 68.7
  Top Layer w0.35: LD14.3@92.28,38.22 LD14.8@92.28,53.46
  Bottom Layer w0.35: U8.17@43.59,53.48 49.27,47.8 ; 50.49,46.58 49.27,47.8 ; v1(92.28,46.21) 50.86,46.21 49.27,47.8
DIGIT-5-4: LD20.3 LD20.8 U9.17 | length 68.7
  Top Layer w0.35: LD20.3@92.28,18.68 LD20.8@92.28,33.92
  Bottom Layer w0.35: U9.17@43.59,33.94 49.27,28.26 ; 50.49,27.04 49.27,28.26 ; v1(92.28,26.67) 50.86,26.67 49.27,28.26
DIGIT-6-1: LD1.3 LD1.8 U5.22 | length 41.1
  Top Layer w0.35: LD1.3@79.28,77.3 v1(79.28,87.78) LD1.8@79.28,92.54
  Bottom Layer w0.35: U5.22@56.29,92.56 56.29,90.96 59.04,88.21 71.98,88.21 72.64,88.21 73,87.85 ; 73,87.78 v1(79.28,87.78)
DIGIT-6-2: LD7.3 LD7.8 U6.22 | length 41.3
  Top Layer w0.35: LD7.3@79.28,57.76 v1(79.28,68.24) LD7.8@79.28,73
  Bottom Layer w0.35: U6.22@56.29,73.02 56.29,71.22 58.84,68.67 71.94,68.67 72.94,68.67 73.37,68.24 v1(79.28,68.24)
DIGIT-6-3: LD13.3 LD13.8 U8.22 | length 41.2
  Top Layer w0.35: LD13.3@79.28,38.22 79.24,38.26 v1(79.24,48.74) 79.24,53.42 LD13.8@79.28,53.46
  Bottom Layer w0.35: U8.22@56.29,53.48 56.29,51.86 59.02,49.13 70.44,49.13 73.46,49.13 73.85,48.74 v1(79.24,48.74) v1@79.28,48.7
DIGIT-6-4: LD19.3 LD19.8 U9.22 | length 42
  Top Layer w0.35: LD19.3@79.28,18.68 v1(79.28,29.16) LD19.8@79.28,33.92
  Bottom Layer w0.35: U9.22@56.29,33.94 56.29,31.51 58.64,29.16 59.56,29.16 69.68,29.16 70.07,29.55 74.5,29.55 74.89,29.16 v1(79.28,29.16)
DOUBLE-DISP-1: R6.2 U10.10 | length 23.8
  Top Layer w0.35: R6.2@18.61,88.46 20.13,88.46 21.25,89.58 v1@23.78,89.58 ; U10.10@37.13,88.14 38.7,88.14 39.12,88.56 v1(39.12,89.02)
  Bottom Layer w0.35: v1(23.78,89.52) 23.82,89.52 23.82,89.48 24.28,89.02 37.37,89.02 v1(39.12,89.02)
DOUBLE-DISP-2: R21.2 U11.10 | length 23.9
  Top Layer w0.35: R21.2@18.61,68.92 20.13,68.92 21.25,70.04 23.78,70.04 v1(23.78,69.98) ; U11.10@37.13,68.6 38.7,68.6 39.12,69.02 v1(39.12,69.48)
  Bottom Layer w0.35: v1(23.78,69.98) 24.28,69.48 v1(39.12,69.48)
DOUBLE-DISP-3: R36.2 U12.10 | length 23.9
  Top Layer w0.35: R36.2@18.61,49.38 20.13,49.38 21.25,50.5 23.78,50.5 v1(23.78,50.44) ; U12.10@37.13,49.06 38.7,49.06 39.12,49.48 v1(39.12,49.94)
  Bottom Layer w0.35: v1(23.78,50.44) 24.28,49.94 36.75,49.94 v1(39.12,49.94)
DOUBLE-DISP-4: R51.2 U13.10 | length 24
  Top Layer w0.35: R51.2@18.61,29.84 20.13,29.84 21.25,30.96 23.78,30.96 v1(23.78,30.9) ; U13.10@37.13,29.52 38.7,29.52 39.12,29.94 v1(39.12,30.4)
  Bottom Layer w0.35: v1(23.78,30.9) v1@23.84,30.9 ; v1@23.78,30.96 v1@23.84,30.9 ; v1(39.12,30.4) 24.34,30.4 v1@23.84,30.9
FREE-1: R15.2 U10.15 | length 21.7
  Top Layer w0.35: R15.2@18.61,92.44 19.124,92.44 19.794,91.77 21.476,91.77 21.996,91.25 23.33,91.25 v1(23.33,91.28) ; U10.15@33.23,90.44 33.23,91.9 33.67,92.34 v1(34.82,92.34)
  Bottom Layer w0.35: v1(23.33,91.28) 24.79,91.28 25.95,90.12 33.2,90.12 34.82,91.74 v1(34.82,92.34)
FREE-2: R30.2 U11.15 | length 21.8
  Top Layer w0.35: R30.2@18.61,72.9 19.124,72.9 19.794,72.23 21.476,72.23 21.996,71.71 23.33,71.71 v1(23.33,71.74) ; U11.15@33.23,70.9 33.23,72.36 33.67,72.8 v1(34.82,72.8)
  Bottom Layer w0.35: v1(23.33,71.74) 24.76,71.74 25.65,70.85 33.54,70.85 34.82,72.13 v1(34.82,72.8) 34.78,72.84 v1@34.62,72.84
FREE-3: R45.2 U12.15 | length 21.9
  Top Layer w0.35: R45.2@18.61,53.36 19.124,53.36 19.794,52.69 21.476,52.69 21.996,52.17 23.33,52.17 v1(23.33,52.2) ; U12.15@33.23,51.36 33.23,52.82 33.67,53.26 v1(34.82,53.26)
  Bottom Layer w0.35: v1(23.33,52.2) 24.85,52.2 25.9,51.15 33.81,51.15 34.82,52.16 v1(34.82,53.26)
FREE-4: R60.2 U13.15 | length 21.9
  Top Layer w0.35: R60.2@18.61,33.82 19.124,33.82 19.794,33.15 21.476,33.15 21.996,32.63 23.33,32.63 v1(23.33,32.66) ; U13.15@33.23,31.82 33.23,33.28 33.67,33.72 v1(34.82,33.72)
  Bottom Layer w0.35: v1(23.33,32.66) 24.77,32.66 25.93,31.5 33.5,31.5 34.82,32.82 v1(34.82,33.72)
GND: C2.2 C3.2 C4.2 C5.2 C6.2 C7.2 C8.2 C9.2 C10.2 C11.2 C12.2 C13.2 C14.2 C15.2 C16.2 C17.2 C18.2 C19.2 C20.2 C21.2 C22.2 C23.2 C24.2 C25.2 C26.2 C27.2 C28.2 C29.2 C30.2 C31.2 C32.2 C33.2 C34.2 C35.2 C36.2 C37.2 C38.2 C39.2 C40.2 C41.2 C42.2 C43.2 C44.2 C45.2 C46.2 C47.2 C48.2 C49.2 C50.2 C51.2 Con1.3 Con2.3 Con3.3 Con4.3 D5.K D6.K D7.K D8.K J1.4 J1.6 J1.7 J1.8 J2.4 J2.6 J2.7 J2.8 J3.4 J3.6 J3.7 J3.8 J4.4 J4.6 J4.7 J4.8 R13.2 R14.2 R28.2 R29.2 R43.2 R44.2 R58.2 R59.2 R61.2 R62.1 R63.1 R64.2 T1.2 T4.2 T5.2 T6.2 T9.2 T10.2 T11.2 T14.2 T15.2 T16.2 T19.2 T20.2 U1.4 U2.4 U3.4 U4.4 U5.28 U6.28 U8.28 U9.28 U10.6 U10.29 U11.6 U11.29 U12.6 U12.29 U13.6 U13.29 X2.1 | length 874.4
  Top Layer w0.4: U13.29@26.13,25.52 29.69,25.52 30.67,24.54 v1(31.16,24.54) 34.01,24.54 35.79,26.32 U13.6@37.13,26.32 41.07,26.32 C45.2@42.59,27.84 ; U12.29@26.13,45.06 29.69,45.06 30.67,44.08 v1(31.16,44.08) 34.01,44.08 35.79,45.86 U12.6@37.13,45.86 41.07,45.86 C35.2@42.59,47.38 ; U11.29@26.13,64.6 29.69,64.6 30.67,63.62 v1(31.16,63.62) 34.01,63.62 35.79,65.4 U11.6@37.13,65.4 41.07,65.4 C25.2@42.59,66.92 ; U10.29@26.13,84.14 29.69,84.14 30.67,83.16 v1(31.16,83.16) 34.01,83.16 35.79,84.94 U10.6@37.13,84.94 41.07,84.94 C15.2@42.59,86.46
  Top Layer w0.5: C48.2@27.74,4.97 28.21,4.5 v1(28.97,4.5) U4.4@30.58,4.5 ; v1(33.794,6.58) 32.66,7.714 32.66,9.28 C42.2@33.92,10.54 C42.2@33.93,10.55 ; C42.2@33.93,10.12 C42.2@33.93,10.55 ; C50.2@38.77,10.51 37.51,11.77 34.6,11.77 33.93,11.1 C42.2@33.93,10.55 ; 42.27,94.11 42.27,91.42 43.17,90.52 ; 43.98,90.47 44.86,91.35 44.86,92.18 ; 44.86,91.53 44.86,92.18 ; 44.86,93.56 44.86,92.18 ; v1@53.79,10.83 C46.2@55.09,10.83 ; 54.14,4.475 54.39,4.225 54.744,4.225 55.415,3.554 55.754,3.554 ; C38.2@58.74,4.97 59.21,4.5 v1(59.97,4.5) U3.4@61.58,4.5 ; v1(64.794,6.58) 63.66,7.714 63.66,9.28 C32.2@64.93,10.55 ; C32.2@64.93,10.12 C32.2@64.93,10.55 ; C40.2@69.77,10.51 68.51,11.77 65.6,11.77 64.93,11.1 C32.2@64.93,10.55 ; v1@84.79,10.83 C36.2@86.09,10.83 ; 84.92,4.475 85.17,4.225 85.729,4.225 86.4,3.554 86.754,3.554 ; C28.2@89.75,4.98 90.22,4.51 v1(90.98,4.51) U2.4@92.59,4.51 ; v1(95.804,6.59) 94.67,7.724 94.67,9.29 C22.2@95.94,10.56 ; C22.2@95.94,10.13 C22.2@95.94,10.56 ; C30.2@100.78,10.52 99.52,11.78 96.61,11.78 95.94,11.11 C22.2@95.94,10.56 ; v1@115.8,10.84 C26.2@117.1,10.84 ; 116.13,4.475 116.38,4.225 116.744,4.225 117.415,3.554 117.754,3.554 ; C18.2@120.74,4.96 121.21,4.49 v1(121.97,4.49) U1.4@123.58,4.49 ; v1(126.794,6.57) 125.66,7.704 125.66,9.27 C12.2@126.93,10.54 ; C12.2@126.93,10.11 C12.2@126.93,10.54 ; C20.2@131.77,10.5 130.51,11.76 127.6,11.76 126.93,11.09 C12.2@126.93,10.54 ; v1@146.79,10.82 C16.2@148.09,10.82
  Top Layer w1: Con4.3@2.3,22.46 3.75,22.46 6.83,25.54 T16.2@11.04,25.54 ; Con3.3@2.3,42 3.75,42 6.83,45.08 T11.2@11.04,45.08 ; Con2.3@2.3,61.54 3.75,61.54 6.83,64.62 T6.2@10.7,64.62 ; Con1.3@2.3,81.08 3.75,81.08 6.83,84.16 T1.2@10.7,84.16 ; C44.2@11.23,23.23 11.04,23.42 T16.2@11.04,25.54 ; C24.2@11.23,62.31 11.23,60.88 12.09,60.02 14.79,60.02 16.95,62.18 C23.2@18.76,62.18 18.76,63.25 ; C14.2@11.23,81.85 11.23,80.42 12.09,79.56 14.79,79.56 16.95,81.72 C13.2@18.76,81.72 18.76,82.79 ; C51.2@11.27,35.1 11.27,33.01 T20.2@11.06,32.8 11.38,32.48 C49.2@11.38,30.45 11.38,29.35 11.04,29.01 T19.2@11.04,28.1 T16.2@11.04,25.54 ; C51.2@11.31,35.06 11.31,39.7 12.09,40.48 ; 12.39,59.95 11.27,58.83 C41.2@11.27,54.64 11.27,52.55 T15.2@11.06,52.34 11.38,52.02 C39.2@11.38,49.99 11.38,48.89 11.04,48.55 T14.2@11.04,47.64 T11.2@11.04,45.08 ; C47.2@18.76,25.36 18.76,24.17 ; C37.2@18.76,44.9 18.76,43.71 ; C27.2@18.76,64.44 18.76,63.25 ; C17.2@18.76,83.98 18.76,82.79 ; C2.2@19.33,11.95 19.33,11.33 25.7,4.96 C48.2@27.6,4.96 ; C2.2@19.745,12.365 v1(16.441,15.669) 14.79,17.32 14.79,20.94 16.95,23.1 C43.2@18.76,23.1 18.76,24.17 ; v1(21.04,24.19) 21.02,24.17 18.76,24.17 ; v1(21.04,43.73) 21.02,43.71 18.76,43.71 ; v1(21.04,63.27) 21.02,63.25 18.76,63.25 ; v1(21.04,82.81) 21.02,82.79 18.76,82.79 ; 26.666,3.564 26.872,3.77 ; D8.K@26.872,2.41 26.872,3.77 ; C48.2@27.58,4.98 C48.2@27.6,4.96 ; C48.2@27.715,4.845 C48.2@27.6,4.96 ; C48.2@27.74,4.87 26.872,4.002 26.872,3.77 ; R62.1@29.27,74.95 v1(29.27,76.79) ; R63.1@29.53,55.62 v1@29.53,57.16 ; v1(29.65,37.97) 29.65,37.95 30.96,36.64 R64.2@30.96,36.025 ; C50.2@38.77,10.51 40.27,10.51 42.27,8.51 44.98,8.51 44.98,6.54 R58.2@45.14,6.38 ; 42.27,94.11 43.3,95.14 43.48,95.14 44.86,93.76 44.86,93.56 44.85,93.56 ; C45.2@42.59,27.84 42.61,27.86 C9.2@45.52,27.86 ; C35.2@42.59,47.38 42.61,47.4 C10.2@45.52,47.4 ; C25.2@42.59,66.92 42.61,66.94 C5.2@45.52,66.94 ; C15.2@42.59,86.46 42.61,86.48 C6.2@45.52,86.48 ; 43.555,90.175 44.17,89.56 C7.2@46.38,89.56 46.38,88.52 45.52,87.66 C6.2@45.52,86.48 ; J4.8@43.71,11.05 46.25,11.05 J4.4@48.79,11.05 ; C8.2@46.38,30.94 46.38,29.9 45.52,29.04 C9.2@45.52,27.86 ; C11.2@46.38,50.48 46.38,49.44 45.52,48.58 C10.2@45.52,47.4 ; C4.2@46.38,70.02 46.38,68.98 45.52,68.12 C5.2@45.52,66.94 ; R59.2@49.48,2.13 50.59,2.13 v1@51,2.54 ; v1(51,2.57) 52.905,4.475 54.14,4.475 ; 55.754,3.554 57.656,3.554 57.872,3.77 ; D7.K@57.872,2.41 57.872,3.77 ; C38.2@58.58,4.98 C38.2@58.715,4.845 ; C38.2@58.74,4.87 57.872,4.002 57.872,3.77 ; v1(60.1,67.48) 55.99,63.37 49.29,63.37 45.72,66.94 C5.2@45.52,66.94 ; v1(60.14,87.01) 56.16,83.03 49.46,83.03 46.01,86.48 C6.2@45.52,86.48 ; v1(60.59,47.91) 56.73,44.05 49,44.05 45.65,47.4 C10.2@45.52,47.4 ; v1(60.97,28.28) 60.97,28.3 57.1,24.43 48.95,24.43 C9.2@45.52,27.86 ; C40.2@69.77,10.51 71.27,10.51 73.27,8.51 75.98,8.51 75.98,6.54 R43.2@76.14,6.38 ; v1(71.53,28.36) U9.28@71.53,33.94 ; v1(71.53,47.9) U8.28@71.53,53.48 ; v1(71.53,67.44) U6.28@71.53,73.02 ; v1(71.53,86.98) U5.28@71.53,92.56 ; J3.8@74.71,11.05 77.25,11.05 J3.4@79.79,11.05 ; R44.2@80.48,2.13 81.59,2.13 v1@82,2.54 ; v1(82,2.57) 83.905,4.475 84.92,4.475 ; 86.754,3.554 88.656,3.554 88.882,3.78 ; D6.K@88.882,2.42 88.882,3.78 ; C28.2@89.59,4.99 C28.2@89.725,4.855 ; C28.2@89.75,4.88 88.882,4.012 88.882,3.78 ; C30.2@100.78,10.52 102.28,10.52 104.28,8.52 106.99,8.52 106.99,6.55 R28.2@107.15,6.39 ; J2.8@105.72,11.06 108.26,11.06 J2.4@110.8,11.06 ; R29.2@111.49,2.14 112.6,2.14 v1@113.01,2.55 ; v1(113.01,2.58) 114.905,4.475 116.13,4.475 ; 117.754,3.554 119.666,3.554 119.872,3.76 ; D5.K@119.872,2.4 119.872,3.76 ; C18.2@120.58,4.97 C18.2@120.715,4.835 ; C18.2@120.74,4.86 119.872,3.992 119.872,3.76 ; C20.2@131.77,10.5 133.27,10.5 135.27,8.5 J1.7@137.98,8.5 137.98,6.53 R13.2@138.14,6.37 ; J1.8@136.71,11.04 J1.6@139.25,11.04 J1.4@141.79,11.04 ; R14.2@142.48,2.12 143.59,2.12 v1@144,2.53 ; T11.2@11.04,45.08 11.04,42.96 11.23,42.77 11.23,41.34 12.09,40.48 ; 12.09,40.48 14.79,40.48 16.95,42.64 C33.2@18.76,42.64 18.76,43.71 ; C48.2@27.6,4.96 C48.2@27.73,4.96 ; C48.2@27.6,4.96 C48.2@27.73,4.96 ; C48.2@27.6,4.96 C48.2@27.73,4.96 ; v1@29.53,57.16 v1(29.57,57.2) v1@29.53,57.16
  Top Layer w2: C2.2@19.33,11.95 14.51,16.77 14.51,20.02 13.96,20.57 12.1,20.57 10.7,21.97 10.7,28.1 10.7,35.06 10.7,45.08 10.7,52.34 10.7,64.62 10.7,74.18 10.7,84.16 10.7,89.07 10.7,95.64 12.13,97.07 41.37,97.07 43.3,95.14
  Bottom Layer w0.5: v1(28.97,4.5) 31.05,6.58 v1@33.63,6.58 ; J4.4@48.79,11.04 49.99,9.84 52.8,9.84 v1(53.78,10.82) ; J4.4@48.79,11.05 J4.4@48.795,11.045 ; v1(59.97,4.5) 62.05,6.58 v1@64.63,6.58 ; J3.4@79.79,11.05 79.795,11.045 81,9.84 83.8,9.84 v1(84.78,10.82) v1@84.79,10.83 ; v1(90.98,4.51) 93.06,6.59 v1@95.64,6.59 ; J2.4@110.8,11.06 110.805,11.055 112.02,9.84 114.8,9.84 v1(115.79,10.83) ; v1(121.97,4.49) 124.05,6.57 v1@126.63,6.57 ; J1.4@141.79,11.04 142.99,9.84 145.81,9.84 v1(146.78,10.81) ; v1@33.63,6.58 v1(33.794,6.58) v1@33.63,6.58 ; v1@64.63,6.58 v1(64.794,6.58) v1@64.63,6.58 ; v1@95.64,6.59 v1(95.804,6.59) v1@95.64,6.59 ; v1@126.63,6.57 v1(126.794,6.57) v1@126.63,6.57
  Bottom Layer w1: C3.2@11.73,15.71 11.79,15.65 v1@16.441,15.65 ; C2.2@19.33,11.95 21.6,9.68 X2.1@21.6,4.87 ; v1(21.04,24.19) 25.14,24.19 26.2,25.25 28.975,25.25 29.685,24.54 v1(31.16,24.54) ; v1(21.04,43.73) 25.14,43.73 26.2,44.79 28.975,44.79 29.685,44.08 v1(31.16,44.08) 31.47,43.77 31.47,41.56 29.65,39.74 v1(29.65,37.97) ; v1(21.04,63.27) 25.14,63.27 26.2,64.33 28.975,64.33 29.685,63.62 v1(31.16,63.62) 31.37,63.41 31.37,59 v1(29.57,57.2) ; v1(21.04,82.81) 25.14,82.81 26.2,83.87 28.975,83.87 29.685,83.16 v1(31.16,83.16) 31.63,82.69 31.63,79.15 v1(29.27,76.79) ; J4.7@44.98,8.51 44.98,9.78 J4.6@46.25,11.05 ; v1(51,2.57) 51,2.6 52.38,3.98 52.38,5.38 54.48,7.48 54.48,10.12 v1(53.78,10.82) 53.71,10.89 v1@53.71,10.9 ; v1(60.1,67.48) 71.49,67.48 71.49,67.52 v1@71.44,67.57 ; v1(60.14,87.01) 71.5,87.01 v1(71.53,86.98) ; v1(60.59,47.91) 71.52,47.91 v1@71.52,48.08 ; v1(60.97,28.28) 71.45,28.28 v1(71.53,28.36) ; J3.7@75.98,8.51 75.98,9.78 J3.6@77.25,11.05 ; v1(82,2.57) 82,2.6 83.38,3.98 83.38,5.38 85.48,7.48 85.48,10.12 v1(84.78,10.82) 84.71,10.89 v1@84.71,10.9 ; J2.7@106.99,8.52 106.99,9.79 J2.6@108.26,11.06 ; v1(113.01,2.58) 113.01,2.61 114.39,3.99 114.39,5.39 116.49,7.49 116.49,10.13 v1(115.79,10.83) 115.72,10.9 v1@115.72,10.91 ; J1.7@137.98,8.5 137.98,9.77 J1.6@139.25,11.04 ; v1(144,2.56) 144,2.59 145.38,3.97 145.38,5.37 147.48,7.47 147.48,10.11 v1(146.78,10.81) 146.71,10.88 v1@146.71,10.89
ID-0-1: U5.12 U10.38 | length 17.7
  Top Layer w0.35: U10.38@30.83,79.44 30.83,77.45 33.54,74.74 42.35,74.74 43.59,75.98 U5.12@43.59,77.32
ID-0-2: U6.12 U11.38 | length 17.7
  Top Layer w0.35: U11.38@30.83,59.9 30.83,57.91 33.54,55.2 42.35,55.2 43.59,56.44 U6.12@43.59,57.78
ID-0-3: U8.12 U12.38 | length 17.7
  Top Layer w0.35: U12.38@30.83,40.36 30.83,38.37 33.54,35.66 42.35,35.66 43.59,36.9 U8.12@43.59,38.24
ID-0-4: U9.12 U13.38 | length 17.7
  Top Layer w0.35: U13.38@30.83,20.82 30.83,18.83 33.54,16.12 42.35,16.12 43.59,17.36 U9.12@43.59,18.7
ID-1-1: U5.11 U10.39 | length 23.2
  Top Layer w0.35: U10.39@31.63,79.44 31.63,77.5 33.84,75.29 41.57,75.29 42.37,76.09 ; 41.65,75.37 42.37,76.09 ; U5.11@46.13,77.32 46.13,78.49 45.66,78.96 43.66,78.96 ; 42.37,76.09 42.37,78.5 42.83,78.96 43.13,78.96 ; 43.13,78.96 43.66,78.96 ; 43.13,78.96 43.66,78.96
ID-1-2: U6.11 U11.39 | length 23.2
  Top Layer w0.35: U11.39@31.63,59.9 31.63,57.96 33.84,55.75 41.57,55.75 42.37,56.55 ; 41.65,55.83 42.37,56.55 ; U6.11@46.13,57.78 46.13,58.95 45.66,59.42 43.66,59.42 ; 42.37,56.55 42.37,58.96 42.83,59.42 43.13,59.42 ; 43.13,59.42 43.66,59.42 ; 43.13,59.42 43.66,59.42
ID-1-3: U8.11 U12.39 | length 23.2
  Top Layer w0.35: U12.39@31.63,40.36 31.63,38.42 33.84,36.21 41.57,36.21 42.37,37.01 ; 41.65,36.29 42.37,37.01 ; U8.11@46.13,38.24 46.13,39.41 45.66,39.88 43.66,39.88 ; 42.37,37.01 42.37,39.42 42.83,39.88 43.13,39.88 ; 43.13,39.88 43.66,39.88 ; 43.13,39.88 43.66,39.88
ID-1-4: U9.11 U13.39 | length 23.2
  Top Layer w0.35: U13.39@31.63,20.82 31.63,18.88 33.84,16.67 41.57,16.67 42.37,17.47 ; 41.65,16.75 42.37,17.47 ; U9.11@46.13,18.7 46.13,19.87 45.66,20.34 43.66,20.34 ; 42.37,17.47 42.37,19.88 42.83,20.34 43.13,20.34 ; 43.13,20.34 43.66,20.34 ; 43.13,20.34 43.66,20.34
ID-2-1: U5.13 U10.40 | length 12.4
  Top Layer w0.35: U10.40@32.43,79.44 32.43,77.56 34.07,75.92 40.82,75.92 41.05,76.15 U5.13@41.05,77.32
ID-2-2: U6.13 U11.40 | length 12.4
  Top Layer w0.35: U11.40@32.43,59.9 32.43,58.02 34.07,56.38 40.82,56.38 41.05,56.61 U6.13@41.05,57.78
ID-2-3: U8.13 U12.40 | length 12.4
  Top Layer w0.35: U12.40@32.43,40.36 32.43,38.48 34.07,36.84 40.82,36.84 41.05,37.07 U8.13@41.05,38.24
ID-2-4: U9.13 U13.40 | length 12.4
  Top Layer w0.35: U13.40@32.43,20.82 32.43,18.94 34.07,17.3 40.82,17.3 41.05,17.53 U9.13@41.05,18.7
ID-3-1: U5.14 U10.41 | length 6.9
  Top Layer w0.35: U10.41@33.23,79.44 33.23,78.23 34.14,77.32 U5.14@38.51,77.32
ID-3-2: U6.14 U11.41 | length 6.9
  Top Layer w0.35: U11.41@33.23,59.9 33.23,58.69 34.14,57.78 U6.14@38.51,57.78
ID-3-3: U8.14 U12.41 | length 6.9
  Top Layer w0.35: U12.41@33.23,40.36 33.23,39.15 34.14,38.24 U8.14@38.51,38.24
ID-3-4: U9.14 U13.41 | length 6.9
  Top Layer w0.35: U13.41@33.23,20.82 33.23,19.61 34.14,18.7 U9.14@38.51,18.7
ID-4-1: U5.10 U10.2 | length 14
  Top Layer w0.35: U10.2@37.13,81.74 45.13,81.74 48.67,78.2 48.67,77.33 U5.10@48.59,77.25
ID-4-2: U6.10 U11.2 | length 13.6
  Top Layer w0.35: U11.2@37.13,62.2 44.6,62.2 48.67,58.13 U6.10@48.67,57.78
ID-4-3: U8.10 U12.2 | length 13.9
  Top Layer w0.35: U12.2@37.13,42.66 45.11,42.66 48.67,39.1 U8.10@48.67,38.24
ID-4-4: U9.10 U13.2 | length 13.8
  Top Layer w0.35: U13.2@37.13,23.12 45.04,23.12 48.67,19.49 U9.10@48.67,18.7
ID-5-1: U5.6 U10.3 | length 27.9
  Top Layer w0.35: U10.3@37.13,82.54 45.79,82.54 49.92,78.41 49.92,77 ; 49.94,77 49.94,75.82 50.56,75.2 58.11,75.2 58.83,75.92 U5.6@58.83,77.32
ID-5-2: U6.6 U11.3 | length 27.8
  Top Layer w0.35: U11.3@37.13,63 45.61,63 49.94,58.67 49.94,56.28 50.56,55.66 58.11,55.66 58.83,56.38 U6.6@58.83,57.78
ID-5-3: U8.6 U12.3 | length 27.9
  Top Layer w0.35: U12.3@37.13,43.46 45.68,43.46 49.94,39.2 49.94,38.67 49.94,36.74 50.56,36.12 58.11,36.12 58.83,36.84 U8.6@58.83,38.24
ID-5-4: U9.6 U13.3 | length 27.8
  Top Layer w0.35: U13.3@37.13,23.92 45.57,23.92 49.94,19.55 49.94,17.2 50.56,16.58 58.11,16.58 58.83,17.3 U9.6@58.83,18.7
ID-6-1: U5.5 U10.4 | length 32.8
  Top Layer w0.35: U10.4@37.13,83.34 45.86,83.34 49.5,79.7 54.5,79.7 55.04,79.16 55.04,76.33 55.53,75.84 56.88,75.84 57.58,76.54 57.58,78.35 58.37,79.14 60.53,79.14 61.37,78.3 U5.5@61.37,77.32
ID-6-2: U6.5 U11.4 | length 32.3
  Top Layer w0.35: U11.4@37.13,63.8 45.66,63.8 49.62,59.84 54.08,59.84 55.04,58.88 55.04,56.79 55.53,56.3 56.88,56.3 57.58,57 57.58,58.81 58.37,59.6 60.53,59.6 61.37,58.76 U6.5@61.37,57.78
ID-6-3: U8.5 U12.4 | length 32.4
  Top Layer w0.35: U12.4@37.13,44.26 45.84,44.26 49.54,40.56 53.75,40.56 55.04,39.27 ; U8.5@61.37,38.24 61.37,39.22 60.53,40.06 58.37,40.06 57.58,39.27 57.58,37.46 56.88,36.76 55.53,36.76 55.04,37.25 55.04,39.27 ; 55.04,39.27 55.04,39.31 55.04,39.27
ID-6-4: U9.5 U13.4 | length 32.1
  Top Layer w0.35: U13.4@37.13,24.72 45.68,24.72 49.5,20.9 53.5,20.9 55.04,19.36 55.04,17.71 55.53,17.22 56.88,17.22 57.58,17.92 57.58,19.73 58.37,20.52 60.53,20.52 61.37,19.68 U9.5@61.37,18.7
ID-7-1: U5.7 U10.5 | length 22.8
  Top Layer w0.35: U10.5@37.13,84.14 46.14,84.14 50.03,80.25 54.728,80.25 56.29,78.688 U5.7@56.29,77.32
ID-7-2: U6.7 U11.5 | length 22.8
  Top Layer w0.35: U11.5@37.13,64.6 45.86,64.6 49.699,60.761 54.619,60.761 56.25,59.13 56.29,59.13 U6.7@56.29,57.78
ID-7-3: U8.7 U12.5 | length 22.6
  Top Layer w0.35: U12.5@37.13,45.06 46.03,45.06 49.83,41.26 54.28,41.26 56.29,39.25 U8.7@56.29,38.24
ID-7-4: U9.7 U13.5 | length 22.8
  Top Layer w0.35: U13.5@37.13,25.52 45.92,25.52 49.79,21.65 54.67,21.65 56.29,20.03 U9.7@56.29,18.7
LED-A-1: LD1.7 LD2.7 LD3.7 LD4.7 LD5.7 LD6.7 U5.27 | length 89.4
  Bottom Layer w0.35: U5.27@68.99,92.56 68.99,93.64 69.67,94.32 81.82,94.32 ; LD1.7@81.82,92.54 81.82,94.32 ; LD2.7@94.82,92.54 94.82,94.32 ; LD3.7@107.82,92.54 107.82,94.32 ; LD4.7@120.82,92.54 120.82,94.32 ; LD5.7@133.82,92.54 133.82,94.32 ; LD6.7@146.82,92.54 146.82,93.48 145.98,94.32 133.82,94.32 ; 81.82,94.32 94.82,94.32 ; 94.82,94.32 107.82,94.32 ; 107.82,94.32 120.82,94.32 ; 120.82,94.32 133.82,94.32
LED-A-2: LD7.7 LD8.7 LD9.7 LD10.7 LD11.7 LD12.7 U6.27 | length 89.4
  Bottom Layer w0.35: U6.27@68.99,73.02 68.99,74.1 69.67,74.78 81.82,74.78 ; LD7.7@81.82,73 81.82,74.78 ; LD8.7@94.82,73 94.82,74.78 ; LD9.7@107.82,73 107.82,74.78 ; LD10.7@120.82,73 120.82,74.78 ; LD11.7@133.82,73 133.82,74.78 ; LD12.7@146.82,73 146.82,73.94 145.98,74.78 133.82,74.78 ; 81.82,74.78 94.82,74.78 ; 94.82,74.78 107.82,74.78 ; 107.82,74.78 120.82,74.78 ; 120.82,74.78 133.82,74.78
